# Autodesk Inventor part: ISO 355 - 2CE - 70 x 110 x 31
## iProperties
IsCustomPart: 0
Created: 2009-02
Part Number: ISO 355 - 2CE - 70 x 110 x 31
Material: Steel, Mild
Description: Metric Tapered Roller Bearings
Document SubType Name: Modeling
Standard: ISO 355
Designer: 904Chiaki
Standard Revision: First edition 1977-05-01
Standards Organization: ISO
Language: en-US
Size Designation: 2CE - 70 x 110 x 31
Categories: <MemberInstance><Categories><Category DisplayName="Shaft Parts" InternalName="7f7aeb1f-a693-4053-b835-cee3144e0d98" Mnemonic="SHFT"><Category DisplayName="Beari
Density: 1 g/cm^3
Author: 904Chiaki
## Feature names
1. Body [Revolution]
2. Fillet1
3. Roller [Revolution]
4. Rollers [Circular Pattern]
